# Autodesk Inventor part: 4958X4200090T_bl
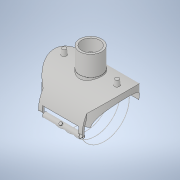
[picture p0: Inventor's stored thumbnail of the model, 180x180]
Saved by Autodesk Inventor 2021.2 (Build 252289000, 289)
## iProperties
Created: 2020-06
Part Number: 4958X4200090T_bl
Material: Generic
Description: Plasson Branch Saddle 200x90
Document SubType Name: Modeling
Designer: KIM
Density: 1 g/cm^3
Appearance: Default
Author: KIM
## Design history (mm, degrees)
derived "4958X4.ipt"
feature "Solid1::4958X4.ipt" dims "ScaleForDerivedMember" = 10
tag "TaggingFeature1"
body "Solid1"
other parameters: "d0" = 295 [user parameter], "d3" = 246.2 [user parameter], "d4" = 109 [user parameter], "d7" = 73 [user parameter], "d9" = 81 [user parameter], "d10" = 0.5 [user parameter], "d11" = 1 [user parameter], "d12" = 27.25 [user parameter], "d13" = 16 [user parameter], "d14" = 8 [user parameter], "d16" = 10 deg [user parameter], "d17" = 10 deg [user parameter], "d19" = 0 [user parameter], "d23" = 0 [user parameter], "d26" = 0 [user parameter], "d27" = 177 [user parameter], "d28" = 0 [user parameter], "d29" = 147.5 [user parameter], "d30" = 0 [user parameter], "d31" = 1 [user parameter], "d32" = 1 [user parameter], "d33" = 19.2 [user parameter], "d34" = 9.6 [user parameter], "d35" = 45 deg [user parameter], "d36" = 147.5 [user parameter], "d37" = 0 [user parameter], "d38" = 5 [user parameter], "d39" = 85 deg [user parameter], "d40" = 27.25 [user parameter], "d41" = 16 [user parameter], "d42" = 107.27273 [user parameter], "d49" = 3 [user parameter], "d50" = 6 [user parameter], "d51" = 5 [user parameter], "d54" = 0 [user parameter], "d57" = 35 deg [user parameter], "d60" = 18.4375 [user parameter], "d61" = 1 [user parameter], "d62" = 90 deg [user parameter], "d63" = 2 [user parameter], "d64" = 0 [user parameter], "d65" = 0 [user parameter], "d68" = 36.875 [user parameter], "d70" = 0.57711 [user parameter], "d71" = 10 deg [user parameter], "d73" = 8.085 [user parameter], "B" = 277 [user parameter], "L" = 295 [user parameter], "LS" = 81 [user parameter], "H1" = 109 [user parameter], "Dt" = 16 [user parameter], "di" = 73 [user parameter], "d72" = 23.1 [user parameter]
